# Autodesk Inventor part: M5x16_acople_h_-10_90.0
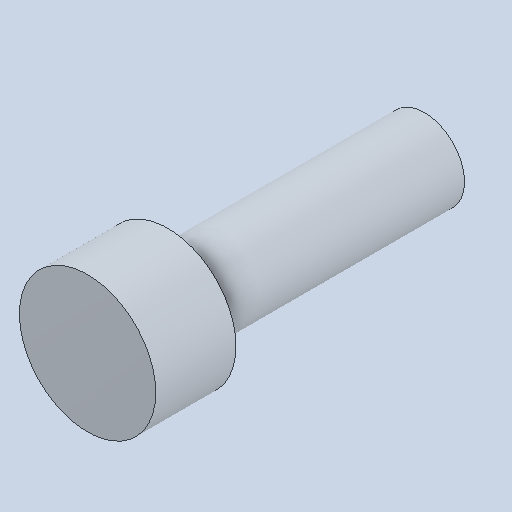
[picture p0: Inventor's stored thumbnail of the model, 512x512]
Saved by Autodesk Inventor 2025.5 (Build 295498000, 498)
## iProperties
Created: 2026-10
Part Number: M5x16_acople_h_-10_90.0
Material: Genérico
Document SubType Name: Modeling
Designer: Luis M
Density: 1 g/cm^3
Appearance: Valor por defecto
Author: Luis M
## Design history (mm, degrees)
feature "Base1"
node "Sólido1"
